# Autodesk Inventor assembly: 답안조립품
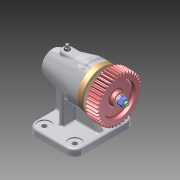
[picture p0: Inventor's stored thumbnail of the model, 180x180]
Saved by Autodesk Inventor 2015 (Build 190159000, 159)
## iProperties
Created: 2024-12
Part Number: 답안조립품
Document SubType Name: Assembly
Designer: 102-5
Author: 102-5
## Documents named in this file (15)
- C:\Users\102-5\Desktop\741204V1005\답안조립품.iam
- C:\Users\102-5\Desktop\741204V1005\가져온 구성요소\그리스 니플 M6x0.75\그리스 니플 M6x0.75.ipt
- C:\Users\102-5\Desktop\741204V1005\본체.ipt
- C:\Users\102-5\Desktop\741204V1005\가져온 구성요소\스퍼기어\스퍼기어.ipt
- C:\Users\102-5\Desktop\741204V1005\가져온 구성요소\스프링 와셔 M8\스프링 와셔 M8.ipt
- C:\Users\102-5\Desktop\741204V1005\가져온 구성요소\실링\실링.ipt
- C:\Users\102-5\Desktop\741204V1005\가져온 구성요소\앵귤러 볼 베어링 7003A\앵귤러 볼 베어링 7003A.ipt
- C:\Users\102-5\Desktop\741204V1005\가져온 구성요소\앵귤러 볼 제어링 7204A\앵귤러 볼 제어링 7204A.ipt
- C:\Users\102-5\Desktop\741204V1005\가져온 구성요소\오일 실 20 32 8\오일 실 20 32 8.ipt
- C:\Users\102-5\Desktop\741204V1005\가져온 구성요소\육각 너트 M8\육각 너트 M8.ipt
- C:\Users\102-5\Desktop\741204V1005\가져온 구성요소\육각 소켓 머리 볼트 M4x10\육각 소켓 머리 볼트 M4x10.ipt
- C:\Users\102-5\Desktop\741204V1005\가져온 구성요소\축\축.ipt
- C:\Users\102-5\Desktop\741204V1005\가져온 구성요소\커버\커버.ipt
- C:\Users\102-5\Desktop\741204V1005\가져온 구성요소\평와셔 M8\평와셔 M8.ipt
- C:\Users\102-5\Desktop\741204V1005\가져온 구성요소\평행 키 4x4x14\평행 키 4x4x14.ipt
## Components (1 placed, 1 different names)
1. 그리스 니플 M6x0.75:1
